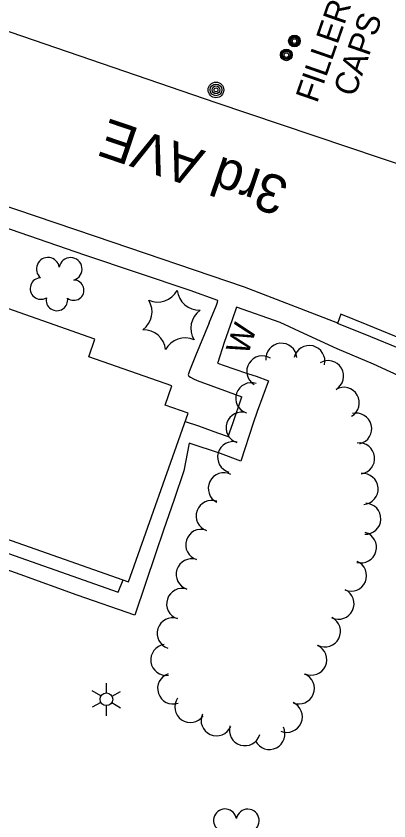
# Model space of a CAD drawing. Extents: x 189384 to 193282, y 256970 to 260388.
# Drawn here: x 190536.2 to 190632.4, y 258279 to 258486.9 of the extents above; entities that cross this region are included whole.
import ezdxf

# ---------------------------------------------------------------- set-up
doc = ezdxf.new("R2010")
doc.units = 0
for name, color, linetype in [('E_DRN_Grate', 7, 'Continuous'), ('E_LAND_Vegetation', 7, 'Continuous'), ('E_MISCPROP', 7, 'Continuous'), ('E_MISCPROP_HvyLine', 7, 'Continuous'), ('E_MISCPROP_Railing', 7, 'Continuous'), ('E_PATH_Sidewalk', 7, 'Continuous'), ('E_RDWY', 7, 'Continuous'), ('E_RDWY_Name', 7, 'Continuous')]:
    doc.layers.add(name, color=color, linetype=linetype)

# ---------------------------------------------------------------- blocks, each defined once
blk = doc.blocks.new('WAL')
at = {"layer": 'E_MISCPROP_Railing'}
blk.add_text('W', height=6, rotation=360, dxfattribs=at).set_placement((-2.3, -3.01))
blk = doc.blocks.new('POLE_1')
at = {"layer": 'E_MISCPROP'}
for radius in [2.02, 1.51, 1.01, 0.504]:
    blk.add_circle((0.03, -0.09), radius, dxfattribs=at)
blk = doc.blocks.new('MHO_4')
at = {"layer": 'E_DRN_Grate'}
for centre, radius in [((0.04, -0.06), 1.5), ((0.04, -0.06), 1.22), ((0.04, -0.07), 0.968), ((0.01, -0.08), 0.605)]:
    blk.add_circle(centre, radius, dxfattribs=at)
blk = doc.blocks.new('FILLER')
at = {"layer": 'E_DRN_Grate'}
for s, p in [('FILLER', (-15.52, 1.33)), ('CAPS', (-10.83, -7.33))]:
    blk.add_text(s, height=6, rotation=0, dxfattribs=at).set_placement(p)
blk = doc.blocks.new('LTP_10')
at = {"layer": 'E_MISCPROP'}
for p, q in [((-0.8, 1.43), (-2, 3.73)), ((0.9, 1.42), (2.27, 3.65)), ((-1.64, 0.07), (-4.24, 0.14)), ((-0.88, -1.42), (-2.24, -3.61)), ((0.76, -1.47), (2, -3.65)), ((1.64, -0.02), (4.16, -0.09))]:
    blk.add_line(p, q, dxfattribs=at)
blk.add_circle((0, 0), 1.64, dxfattribs=at)
blk = doc.blocks.new('TREE_10')
at = {"layer": 'E_LAND_Vegetation'}
for centre, radius, start, end in [((-1.47, 4.28), 2.78, 1.3947, 209.1677), ((3.57, 2.42), 2.97, 278.4238, 139.6577), ((-4.47, 0.2), 2.78, 78.0717, 279.0828), ((3.46, -3.43), 2.97, 196.0746, 79.0479), ((-2.01, -4.2), 2.61, 140.7799, 358.7125)]:
    blk.add_arc(centre, radius, start, end, dxfattribs=at)
blk = doc.blocks.new('PINEL_3')
at = {"layer": 'E_LAND_Vegetation'}
for centre, start, end in [((-8.14, 7.32), 275.2115, 0.9764), ((2.26, 10.71), 215.2115, 300.9764), ((10.41, 3.41), 155.2115, 240.9764), ((-10.4, -3.39), 335.2115, 60.9764), ((8.15, -7.3), 95.2115, 180.9764), ((-2.25, -10.7), 35.2115, 120.9764)]:
    blk.add_arc(centre, 5.72, start, end, dxfattribs=at)

msp = doc.modelspace()

# ---------------------------------------------------------------- linework, layer by layer
at = {"layer": 'E_LAND_Vegetation'}
for centre, start, end in [((190604.65, 258398.4), 5.2159, 185.2005), ((190611.88, 258397.81), 346.3, 166.2847), ((190599.73, 258395.15), 58.1609, 238.1456), ((190616.73, 258393.92), 300.826, 120.8107), ((190596.88, 258388.19), 71.0304, 251.0151), ((190620.76, 258387.03), 299.9462, 119.9308), ((190594.39, 258380.59), 71.6473, 251.632), ((190623.98, 258380.36), 283.8237, 103.8084), ((190592.19, 258372.99), 74.365, 254.3497), ((190624.74, 258372.66), 277.0218, 97.0064), ((190589.78, 258364.93), 63.5741, 243.5588), ((190625.63, 258364.77), 274.699, 94.6837), ((190586.66, 258357.82), 70.2694, 250.2541), ((190626.33, 258357.06), 267.8025, 87.7871), ((190583.96, 258350.34), 72.1148, 252.0995), ((190625.23, 258349.67), 254.2437, 74.2284), ((190581.49, 258342.71), 72.1148, 252.0995), ((190622.65, 258342.37), 246.9706, 66.9553), ((190579.03, 258335.08), 72.1148, 252.0995), ((190619.42, 258335.13), 244.5181, 64.5028), ((190615.91, 258327.97), 243.2378, 63.2225), ((190576.57, 258327.45), 72.1148, 252.0995), ((190574.94, 258320.61), 97.8986, 277.8833), ((190612.38, 258320.67), 245.8284, 65.8131), ((190576.71, 258313.22), 108.3851, 288.3698), ((190609.17, 258313.24), 248.0217, 68.0064), ((190581.14, 258308.45), 145.3603, 325.345), ((190606.08, 258305.89), 246.8037, 66.7884), ((190587.92, 258305), 156.1927, 336.1774), ((190595.23, 258302.45), 163.4313, 343.416), ((190601.58, 258301.47), 206.5654, 26.5501)]:
    msp.add_arc(centre, 4.01, start, end, dxfattribs=at)
at = {"layer": 'E_MISCPROP_HvyLine'}
msp.add_lwpolyline([(190519.92, 258356.75), (190565.21, 258340.79), (190580.56, 258384.37), (190574.62, 258386.46), (190576.35, 258391.38), (190554.92, 258398.93), (190556.52, 258403.48), (190528.12, 258413.48)], dxfattribs=at)
at = {"layer": 'E_MISCPROP_Railing'}
msp.add_lwpolyline([(190585.97, 258407.69), (190582.52, 258399.17), (190580.97, 258395.26), (190580.61, 258394.28), (190580.74, 258393.92), (190581.22, 258393.61), (190581.95, 258393.25), (190582.91, 258392.81), (190594.43, 258388.57)], dxfattribs=at)
at = {"layer": 'E_PATH_Sidewalk'}
for points in [[(190585.97, 258407.69), (190587.91, 258412.22), (190588.16, 258413.04), (190588.26, 258413.47), (190581.14, 258416.05), (190553.89, 258425.19), (190525.18, 258435.09), (190499.48, 258444), (190478.45, 258451.09), (190464.24, 258456.19), (190455.6, 258459.27), (190452.63, 258449.9), (190448.76, 258438.99), (190440.02, 258442.03), (190415.82, 258450.41), (190414.15, 258445.57), (190416.26, 258444.94), (190417.97, 258444.33), (190426.8, 258440.87)], [(190637.09, 258393.08), (190628.45, 258396.98), (190619.09, 258401.01), (190610.45, 258404.89), (190604.32, 258407.76), (190593.06, 258411.71), (190591.96, 258408.5), (190589.85, 258402.63), (190588.22, 258397.43), (190588.17, 258397.28), (190592.12, 258395.85), (190596.17, 258394.51), (190598.13, 258393.88), (190601.35, 258392.72), (190598.44, 258384.78), (190597.39, 258381.79), (190594.21, 258371.94), (190588.97, 258373.96), (190580.89, 258376.6), (190579.47, 258369.42), (190577, 258362.03), (190574.2, 258354.13), (190572.2, 258348.26), (190566.81, 258332.18), (190551.91, 258337.37), (190537.21, 258342.7), (190527, 258346.31)], [(190579.8, 258382.23), (190583.22, 258381.08), (190588.14, 258379.31), (190590.93, 258378.28), (190592.14, 258381.69), (190594.43, 258388.57)], [(190447.5, 258376.79), (190446.21, 258373.14), (190515.45, 258349.47), (190515.86, 258349.44), (190520, 258349.74), (190526.82, 258350.65), (190562.48, 258338.09), (190563.81, 258341.28)]]:
    msp.add_lwpolyline(points, dxfattribs=at)
at = {"layer": 'E_RDWY'}
for points in [[(190619.22, 258407.63), (190595.17, 258416.94), (190556.62, 258429.98), (190500.22, 258449.08), (190500.1, 258449.71), (190499.24, 258452.07), (190497.67, 258453.63), (190495.57, 258454.37), (190493.18, 258455.06), (190490.33, 258456), (190486.92, 258456.97), (190483.95, 258457.86), (190481.04, 258458.75), (190478.47, 258459.37), (190476.18, 258459.79), (190474.85, 258460.06), (190473.9, 258460.08), (190472.91, 258459.82), (190471.97, 258459.48), (190471.38, 258459.25), (190446.28, 258468.19), (190413.73, 258479.4), (190363.26, 258503.28)], [(190665.36, 258436.82), (190662.25, 258439.74), (190638.68, 258447.38), (190587.81, 258464.56), (190531.81, 258483.75), (190491.4, 258496.8)], [(190616.68, 258225.7), (190626.92, 258248.31), (190635.07, 258266.98), (190648.32, 258297.01), (190666.22, 258338.37), (190675.94, 258361.41), (190677.12, 258364.96), (190677.58, 258367.44), (190677.79, 258369.25), (190677.84, 258370.35), (190676.64, 258376.89), (190675.7, 258379.42), (190674.33, 258381.46), (190672.75, 258383.67), (190670.75, 258385.6), (190668.18, 258387.61), (190665.38, 258389), (190662.69, 258390.36), (190659.88, 258391.68), (190647.05, 258398.72), (190637.72, 258402.65), (190626.82, 258407.13), (190619.98, 258409.92), (190619.19, 258407.54)], [(190624.63, 258249.31), (190632.78, 258267.99), (190646.03, 258298.02), (190663.93, 258339.35), (190673.6, 258362.29), (190674.69, 258365.58), (190675.1, 258367.82), (190675.3, 258369.45), (190675.33, 258370.17), (190674.22, 258376.22), (190673.46, 258378.27), (190672.28, 258380.04), (190670.85, 258382.03), (190669.11, 258383.71), (190666.84, 258385.48), (190664.26, 258386.76), (190661.6, 258388.12), (190658.75, 258389.45), (190645.96, 258396.47), (190636.76, 258400.34), (190625.88, 258404.82), (190619.19, 258407.54)]]:
    msp.add_lwpolyline(points, dxfattribs=at)

# ---------------------------------------------------------------- block references
at = {"layer": 'E_DRN_Grate'}
for name, p, rotation in [('FILLER', (190620.21, 258478.46), 70.86176436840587), ('MHO_4', (190607.97, 258480.48), 70.86176458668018), ('MHO_4', (190605.87, 258476.89), 70.86176462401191)]:
    msp.add_blockref(name, p, dxfattribs=dict(at, rotation=rotation))
at = {"layer": 'E_LAND_Vegetation'}
for name, p, xscale, yscale, rotation in [('TREE_10', (190546.84, 258418.07), 1.0000013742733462, 1.000001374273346, 90.72455470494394), ('PINEL_3', (190576.28, 258408.41), 1.0000013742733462, 1.0000013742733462, 90.72455417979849), ('TREE_10', (190592.58, 258275.59), 1.0000013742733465, 1.0000013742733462, 90.72455388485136)]:
    msp.add_blockref(name, p, dxfattribs=dict(at, xscale=xscale, yscale=yscale, rotation=rotation))
at = {"layer": 'E_MISCPROP', "rotation": 70.86176494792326}
msp.add_blockref('POLE_1', (190587.68, 258467.87), dxfattribs=at)
at = {"layer": 'E_MISCPROP', "xscale": 1.0000013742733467, "yscale": 1.0000013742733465, "rotation": 90.72455447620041}
msp.add_blockref('LTP_10', (190559.47, 258310.43), dxfattribs=at)
at = {"layer": 'E_MISCPROP_Railing', "rotation": 71.30380367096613}
msp.add_blockref('WAL', (190593.82, 258402.22), dxfattribs=at)

# ---------------------------------------------------------------- texts
at = {"layer": 'E_RDWY_Name'}
msp.add_text('3rd AVE', height=10, rotation=161.2967, dxfattribs=at).set_placement((190607.08, 258444.63))

doc.saveas('drawing.dxf')
